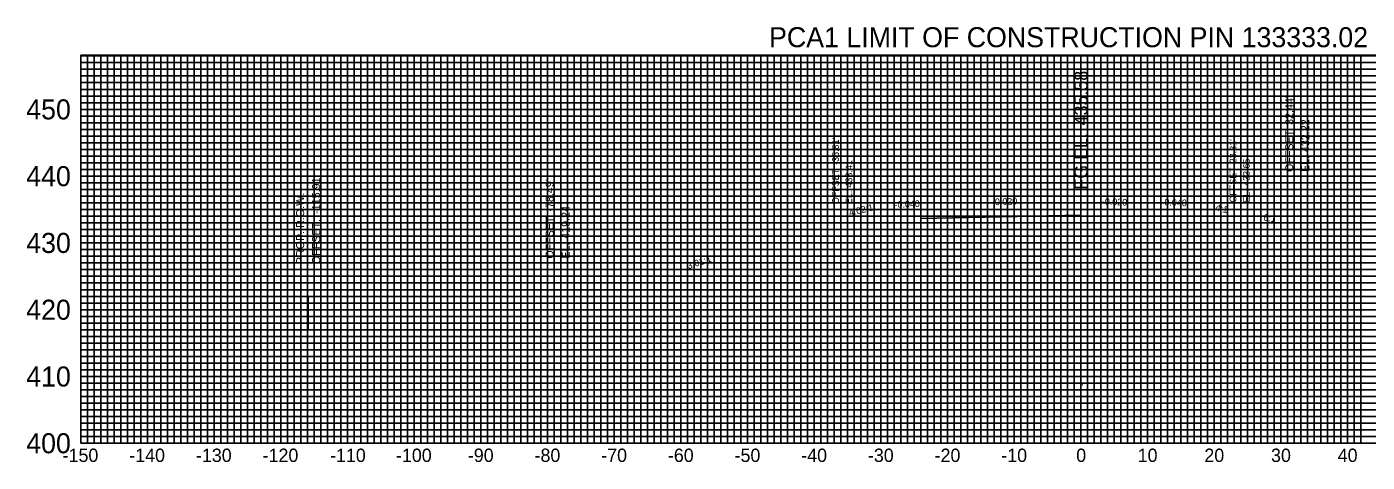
# Model space of a CAD drawing. Extents: x -158 to 158, y 393 to 462.
# Drawn here: x -158.1 to 42.9, y 397.2 to 462.4 of the extents above; entities that cross this region are included whole.
import ezdxf

# ---------------------------------------------------------------- set-up
doc = ezdxf.new("R2010")
doc.units = 0
for name, color, linetype in [('Default', 7, 'Continuous'), ('DES - MODEL - Lines - Ditch Centerline', 7, 'Continuous'), ('DES - MODEL - Lines - Pavement Centerline Subgrade', 7, 'Continuous'), ('DES - PRO - Proposed - Roads', 7, 'Continuous'), ('SUR - DTM - Breaklines', 7, 'Continuous'), ('SUR - DTM - Contours - Major', 7, 'Continuous'), ('SUR - DTM - Graphic Voids', 7, 'Continuous'), ('SUR - DTM - Islands', 7, 'Continuous')]:
    doc.layers.add(name, color=color, linetype=linetype)

msp = doc.modelspace()

# ---------------------------------------------------------------- linework, layer by layer
at = {"layer": 'Default'}
msp.add_circle((0.2, 408.75), 0.012, dxfattribs=at)
msp.add_circle((0.2, 408.75), 0.012, dxfattribs=at)
msp.add_circle((0.2, 408.75), 0.012, dxfattribs=at)
at = {"layer": 'DES - MODEL - Lines - Ditch Centerline'}
msp.add_line((-115.91, 416.97), (-115.91, 421.89), dxfattribs=at)
msp.add_line((-115.91, 416.97), (-115.91, 421.89), dxfattribs=at)
msp.add_line((-115.91, 416.97), (-115.91, 421.89), dxfattribs=at)
at = {"layer": 'DES - MODEL - Lines - Pavement Centerline Subgrade'}
msp.add_circle((0.2, 408.75), 0.012, dxfattribs=at)
msp.add_circle((0.2, 408.75), 0.012, dxfattribs=at)
msp.add_circle((0.2, 408.75), 0.012, dxfattribs=at)
msp.add_circle((0.2, 408.75), 0.012, dxfattribs=at)
msp.add_circle((0.2, 408.75), 0.012, dxfattribs=at)
msp.add_circle((0.2, 408.75), 0.012, dxfattribs=at)
at = {"layer": 'DES - PRO - Proposed - Roads'}
msp.add_line((-24, 433.64), (0, 434.14), dxfattribs=at)
at = {"layer": 'SUR - DTM - Breaklines'}
for p, q in [((-150, 458), (150, 458)), ((-150, 457), (150, 457)), ((-149, 400), (-149, 458.11)), ((-148, 400), (-148, 458.11)), ((-147, 400), (-147, 458.11)), ((-146, 400), (-146, 458.11)), ((-145, 400), (-145, 458.11)), ((-144, 400), (-144, 458.11)), ((-143, 400), (-143, 458.11)), ((-142, 400), (-142, 458.11)), ((-141, 400), (-141, 458.11)), ((-139, 400), (-139, 458.11)), ((-138, 400), (-138, 458.11)), ((-137, 400), (-137, 458.11)), ((-136, 400), (-136, 458.11)), ((-135, 400), (-135, 458.11)), ((-134, 400), (-134, 458.11)), ((-133, 400), (-133, 458.11)), ((-132, 400), (-132, 458.11)), ((-131, 400), (-131, 458.11)), ((-129, 400), (-129, 458.11)), ((-128, 400), (-128, 458.11)), ((-127, 400), (-127, 458.11)), ((-126, 400), (-126, 458.11)), ((-125, 400), (-125, 458.11)), ((-124, 400), (-124, 458.11)), ((-123, 400), (-123, 458.11)), ((-122, 400), (-122, 458.11)), ((-121, 400), (-121, 458.11)), ((-119, 400), (-119, 458.11)), ((-118, 400), (-118, 458.11)), ((-117, 400), (-117, 458.11)), ((-116, 400), (-116, 458.11)), ((-115, 400), (-115, 458.11)), ((-114, 400), (-114, 458.11)), ((-113, 400), (-113, 458.11)), ((-112, 400), (-112, 458.11)), ((-111, 400), (-111, 458.11)), ((-109, 400), (-109, 458.11)), ((-108, 400), (-108, 458.11)), ((-107, 400), (-107, 458.11)), ((-106, 400), (-106, 458.11)), ((-105, 400), (-105, 458.11)), ((-104, 400), (-104, 458.11)), ((-103, 400), (-103, 458.11)), ((-102, 400), (-102, 458.11)), ((-101, 400), (-101, 458.11)), ((-99, 400), (-99, 458.11)), ((-98, 400), (-98, 458.11)), ((-97, 400), (-97, 458.11)), ((-96, 400), (-96, 458.11)), ((-95, 400), (-95, 458.11)), ((-94, 400), (-94, 458.11)), ((-93, 400), (-93, 458.11)), ((-92, 400), (-92, 458.11)), ((-91, 400), (-91, 458.11)), ((-89, 400), (-89, 458.11)), ((-88, 400), (-88, 458.11)), ((-87, 400), (-87, 458.11)), ((-86, 400), (-86, 458.11)), ((-85, 400), (-85, 458.11)), ((-84, 400), (-84, 458.11)), ((-83, 400), (-83, 458.11)), ((-82, 400), (-82, 458.11)), ((-81, 400), (-81, 458.11)), ((-79, 400), (-79, 458.11)), ((-78, 400), (-78, 458.11)), ((-77, 400), (-77, 458.11)), ((-76, 400), (-76, 458.11)), ((-75, 400), (-75, 458.11)), ((-74, 400), (-74, 458.11)), ((-73, 400), (-73, 458.11)), ((-72, 400), (-72, 458.11)), ((-71, 400), (-71, 458.11)), ((-69, 400), (-69, 458.11)), ((-68, 400), (-68, 458.11)), ((-67, 400), (-67, 458.11)), ((-66, 400), (-66, 458.11)), ((-65, 400), (-65, 458.11)), ((-64, 400), (-64, 458.11)), ((-63, 400), (-63, 458.11)), ((-62, 400), (-62, 458.11)), ((-61, 400), (-61, 458.11)), ((-59, 400), (-59, 458.11)), ((-58, 400), (-58, 458.11)), ((-57, 400), (-57, 458.11)), ((-56, 400), (-56, 458.11)), ((-55, 400), (-55, 458.11)), ((-54, 400), (-54, 458.11)), ((-53, 400), (-53, 458.11)), ((-52, 400), (-52, 458.11)), ((-51, 400), (-51, 458.11)), ((-49, 400), (-49, 458.11)), ((-48, 400), (-48, 458.11)), ((-47, 400), (-47, 458.11)), ((-46, 400), (-46, 458.11)), ((-45, 400), (-45, 458.11)), ((-44, 400), (-44, 458.11)), ((-43, 400), (-43, 458.11)), ((-42, 400), (-42, 458.11)), ((-41, 400), (-41, 458.11)), ((-39, 400), (-39, 458.11)), ((-38, 400), (-38, 458.11)), ((-37, 400), (-37, 458.11)), ((-36, 400), (-36, 458.11)), ((-35, 400), (-35, 458.11)), ((-34, 400), (-34, 458.11)), ((-33, 400), (-33, 458.11)), ((-32, 400), (-32, 458.11)), ((-31, 400), (-31, 458.11)), ((-29, 400), (-29, 458.11)), ((-28, 400), (-28, 458.11)), ((-27, 400), (-27, 458.11)), ((-26, 400), (-26, 458.11)), ((-25, 400), (-25, 458.11)), ((-24, 400), (-24, 458.11)), ((-23, 400), (-23, 458.11)), ((-22, 400), (-22, 458.11)), ((-21, 400), (-21, 458.11)), ((-19, 400), (-19, 458.11)), ((-18, 400), (-18, 458.11)), ((-17, 400), (-17, 458.11)), ((-16, 400), (-16, 458.11)), ((-15, 400), (-15, 458.11)), ((-14, 400), (-14, 458.11)), ((-13, 400), (-13, 458.11)), ((-12, 400), (-12, 458.11)), ((-11, 400), (-11, 458.11)), ((-9, 400), (-9, 458.11)), ((-8, 400), (-8, 458.11)), ((-7, 400), (-7, 458.11)), ((-6, 400), (-6, 458.11)), ((-5, 400), (-5, 458.11)), ((-4, 400), (-4, 458.11)), ((-3, 400), (-3, 458.11)), ((-2, 400), (-2, 458.11)), ((-1, 400), (-1, 458.11)), ((1, 400), (1, 458.11)), ((2, 400), (2, 458.11)), ((3, 400), (3, 458.11)), ((4, 400), (4, 458.11)), ((5, 400), (5, 458.11)), ((6, 400), (6, 458.11)), ((7, 400), (7, 458.11)), ((8, 400), (8, 458.11)), ((9, 400), (9, 458.11)), ((11, 400), (11, 458.11)), ((12, 400), (12, 458.11)), ((13, 400), (13, 458.11)), ((14, 400), (14, 458.11)), ((15, 400), (15, 458.11)), ((16, 400), (16, 458.11)), ((17, 400), (17, 458.11)), ((18, 400), (18, 458.11)), ((19, 400), (19, 458.11)), ((21, 400), (21, 458.11)), ((22, 400), (22, 458.11)), ((23, 400), (23, 458.11)), ((24, 400), (24, 458.11)), ((25, 400), (25, 458.11)), ((26, 400), (26, 458.11)), ((27, 400), (27, 458.11)), ((28, 400), (28, 458.11)), ((29, 400), (29, 458.11)), ((31, 400), (31, 458.11)), ((32, 400), (32, 458.11)), ((33, 400), (33, 458.11)), ((34, 400), (34, 458.11)), ((35, 400), (35, 458.11)), ((36, 400), (36, 458.11)), ((37, 400), (37, 458.11)), ((38, 400), (38, 458.11)), ((39, 400), (39, 458.11)), ((41, 400), (41, 458.11)), ((42, 400), (42, 458.11)), ((-150, 456), (150, 456)), ((-150, 455), (150, 455)), ((-150, 454), (150, 454)), ((-150, 453), (150, 453)), ((-150, 452), (150, 452)), ((-150, 451), (150, 451)), ((-150, 449), (150, 449)), ((-150, 448), (150, 448)), ((-150, 447), (150, 447)), ((-150, 446), (150, 446)), ((-150, 445), (150, 445)), ((-150, 444), (150, 444)), ((-150, 443), (150, 443)), ((-150, 442), (150, 442)), ((-150, 441), (150, 441)), ((-150, 439), (150, 439)), ((-150, 438), (150, 438)), ((-150, 437), (150, 437)), ((-150, 436), (150, 436)), ((-150, 435), (150, 435)), ((-150, 434), (150, 434)), ((-150, 433), (150, 433)), ((-150, 432), (150, 432)), ((-150, 431), (150, 431)), ((-150, 429), (150, 429)), ((-150, 428), (150, 428)), ((-150, 427), (150, 427)), ((-150, 426), (150, 426)), ((-150, 425), (150, 425)), ((-150, 424), (150, 424)), ((-150, 423), (150, 423)), ((-150, 422), (150, 422)), ((-150, 421), (150, 421)), ((-150, 419), (150, 419)), ((-150, 418), (150, 418)), ((-150, 417), (150, 417)), ((-150, 416), (150, 416)), ((-150, 415), (150, 415)), ((-150, 414), (150, 414)), ((-150, 413), (150, 413)), ((-150, 412), (150, 412)), ((-150, 411), (150, 411)), ((-150, 409), (150, 409)), ((-150, 408), (150, 408)), ((-150, 407), (150, 407)), ((-150, 406), (150, 406)), ((-150, 405), (150, 405)), ((-150, 404), (150, 404)), ((-150, 403), (150, 403)), ((-150, 402), (150, 402)), ((-150, 401), (150, 401))]:
    msp.add_line(p, q, dxfattribs=at)
at = {"layer": 'SUR - DTM - Contours - Major'}
for p, q in [((-150, 458.11), (150, 458.11)), ((-150, 400), (-150, 458.11)), ((-140, 400), (-140, 458.11)), ((-130, 400), (-130, 458.11)), ((-120, 400), (-120, 458.11)), ((-110, 400), (-110, 458.11)), ((-100, 400), (-100, 458.11)), ((-90, 400), (-90, 458.11)), ((-80, 400), (-80, 458.11)), ((-70, 400), (-70, 458.11)), ((-60, 400), (-60, 458.11)), ((-50, 400), (-50, 458.11)), ((-40, 400), (-40, 458.11)), ((-30, 400), (-30, 458.11)), ((-20, 400), (-20, 458.11)), ((-10, 400), (-10, 458.11)), ((0, 400), (0, 458.11)), ((10, 400), (10, 458.11)), ((20, 400), (20, 458.11)), ((30, 400), (30, 458.11)), ((40, 400), (40, 458.11)), ((-150, 450), (150, 450)), ((-150, 440), (150, 440)), ((-150, 430), (150, 430)), ((-150, 420), (150, 420)), ((-150, 410), (150, 410)), ((-150, 400), (150, 400))]:
    msp.add_line(p, q, dxfattribs=at)

# ---------------------------------------------------------------- texts
at = {"layer": 'DES - MODEL - Lines - Ditch Centerline'}
for s, p in [("-115.91'", (-114.11, 434.36)), ("-115.91'", (-114.11, 434.36)), ("-115.91'", (-114.11, 434.36)), ('PROP. R.O.W.', (-116.51, 426.81)), ('PROP. R.O.W.', (-116.51, 426.81)), ('PROP. R.O.W.', (-116.51, 426.81)), ('OFFSET: ', (-114.11, 426.81)), ('OFFSET: ', (-114.11, 426.81)), ('OFFSET: ', (-114.11, 426.81))]:
    msp.add_text(s, height=1.2, rotation=90, dxfattribs=at).set_placement(p)
at = {"layer": 'SUR - DTM - Graphic Voids'}
for s, height, p in [('PCA1 LIMIT OF CONSTRUCTION PIN 133333.02', 3, (-46.78, 459.31)), ('450', 3, (-158.19, 448.5)), ('440', 3, (-158.19, 438.5)), ('430', 3, (-158.19, 428.5)), ('420', 3, (-158.19, 418.5)), ('410', 3, (-158.19, 408.5)), ('400', 3, (-158.19, 398.5)), ('-150', 2, (-152.73, 397.2)), ('-140', 2, (-142.73, 397.2)), ('-130', 2, (-132.73, 397.2)), ('-120', 2, (-122.73, 397.2)), ('-110', 2, (-112.62, 397.2)), ('-100', 2, (-102.73, 397.2)), ('-90', 2, (-91.95, 397.2)), ('-80', 2, (-81.95, 397.2)), ('-70', 2, (-71.95, 397.2)), ('-60', 2, (-61.95, 397.2)), ('-50', 2, (-51.95, 397.2)), ('-40', 2, (-41.95, 397.2)), ('-30', 2, (-31.95, 397.2)), ('-20', 2, (-21.95, 397.2)), ('-10', 2, (-11.95, 397.2)), ('0', 2, (-0.71, 397.2)), ('10', 2, (8.51, 397.2)), ('20', 2, (18.51, 397.2)), ('30', 2, (28.51, 397.2)), ('40', 2, (38.51, 397.2))]:
    msp.add_text(s, height=height, dxfattribs=at).set_placement(p)
for s, height, p in [("435.58'", 2, (1, 447.6)), ("-35.81'", 1, (-36.31, 441.69)), ("-35.81'", 1, (-36.31, 441.69)), ('FG EL. ', 2, (1, 437.98)), ("23.81'", 1, (23.31, 441.93)), ("23.81'", 1, (23.31, 441.93)), ('433.41', 1, (-34.31, 438.3)), ('433.41', 1, (-34.31, 438.3)), ('433.65', 1, (25.31, 438.54)), ('433.65', 1, (25.31, 438.54)), ('OFFSET ', 1, (-36.31, 435.81)), ('OFFSET ', 1, (-36.31, 435.81)), ('OFFSET ', 1, (23.31, 436.05)), ('OFFSET ', 1, (23.31, 436.05)), ('EL. ', 1, (-34.31, 435.81)), ('EL. ', 1, (-34.31, 435.81)), ('EL. ', 1, (25.31, 436.05)), ('EL. ', 1, (25.31, 436.05))]:
    msp.add_text(s, height=height, rotation=90, dxfattribs=at).set_placement(p)
at = {"layer": 'SUR - DTM - Islands'}
for s, height, rotation, p in [("32.44'", 1.2, 90, (31.84, 447.67)), ('432.22', 1.2, 90, (34.24, 443.6)), ('OFFSET ', 1.2, 90, (31.84, 440.62)), ('EL. ', 1.2, 90, (34.24, 440.62)), ("-78.49'", 1.2, 90, (-79.09, 434.69)), ('-0.040', 1, 2.2906, (-27.94, 435.24)), ('-0.020', 1, 2.2906, (-13.33, 435.63)), ('-0.020', 1, 357.7094, (3.12, 435.73)), ('-0.040', 1, 357.7094, (12.06, 435.64)), ('419.24', 1.2, 90, (-76.69, 430.62)), ('4.02:1', 1, 13.98, (-34.67, 434)), ('4:1', 1, 346.02, (20.09, 434.88)), ('6:1', 1, 350.5895, (27.3, 433.38)), ('OFFSET ', 1.2, 90, (-79.09, 427.64)), ('EL. ', 1.2, 90, (-76.69, 427.64)), ('3.01:1', 1, 18.3753, (-58.87, 426.05))]:
    msp.add_text(s, height=height, rotation=rotation, dxfattribs=at).set_placement(p)

doc.saveas('drawing.dxf')
